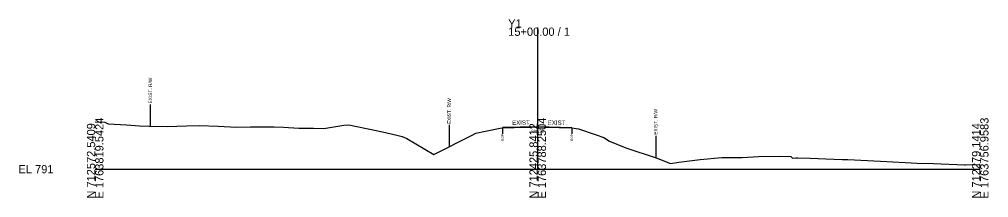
# Model space of a CAD drawing. Extents: x -26 to 1303, y -10 to 9524.
# Drawn here: x -25.7 to 302.8, y 4990.3 to 5050.9 of the extents above; entities that cross this region are included whole.
import ezdxf

# ---------------------------------------------------------------- set-up
doc = ezdxf.new("R2010")
doc.units = 0
for name, color, linetype in [('Default', 7, 'Continuous'), ('Exist Cross Section Cell', 7, 'Continuous'), ('Exist XS Center Line Elevation Label', 7, 'Continuous'), ('Exist XS Ground Line', 7, 'Continuous'), ('Old_Level_10', 7, 'Continuous'), ('Prop CMT Pvmt Surface Overlay', 7, 'Continuous'), ('Prop XS SE Text', 7, 'Continuous')]:
    doc.layers.add(name, color=color, linetype=linetype)

msp = doc.modelspace()

# ---------------------------------------------------------------- linework, layer by layer
at = {"layer": 'Exist Cross Section Cell'}
for p, q in [((150, 5000), (150, 5048.09)), ((0, 5000), (150, 5000)), ((150, 5000), (300, 5000))]:
    msp.add_line(p, q, dxfattribs=at)
at = {"layer": 'Exist XS Ground Line'}
msp.add_lwpolyline([(0, 5016.03), (3.22, 5015.93), (4.41, 5015.43), (10.66, 5015.01), (15.04, 5014.66), (18.3, 5014.61), (24.38, 5014.43), (30.9, 5014.74), (35.22, 5014.87), (41.66, 5014.55), (47.87, 5014.23), (52.7, 5014.36), (60.65, 5014.4), (63.79, 5014.3), (69.08, 5013.96), (74.01, 5013.95), (77.51, 5013.77), (84.24, 5014.96), (85.93, 5015.07), (95.19, 5013.13), (98.37, 5012.39), (102.66, 5011.47), (104.1, 5011.11), (105.64, 5010.41), (114.76, 5004.96), (128.03, 5011.68), (129, 5012.17), (132.35, 5012.88), (137.3, 5013.91), (138.06, 5014.08), (138.75, 5014.13), (139.22, 5014.15), (139.81, 5014.17), (140.7, 5014.19), (141.31, 5014.2), (141.91, 5014.2), (142.91, 5014.22), (144.47, 5014.26), (147.03, 5014.3), (147.61, 5014.31), (149.23, 5014.35), (149.55, 5014.35), (150.11, 5014.36), (151.62, 5014.32), (152.14, 5014.31), (153.37, 5014.3), (154.69, 5014.28), (156.62, 5014.2), (157.25, 5014.17), (157.66, 5014.16), (158.63, 5014.14), (159.58, 5014.11), (160.25, 5014.09), (161.57, 5014.05), (163.79, 5013.64), (169.8, 5011.7), (172.46, 5010.72), (174.33, 5009.51), (179.88, 5007.26), (190.2, 5003.88), (194.99, 5001.89), (197.89, 5002.37), (205.09, 5003.32), (212.36, 5003.92), (219.27, 5003.98), (224.82, 5004.27), (231.89, 5004.35), (235.83, 5004.28), (236.4, 5003.77), (237.53, 5003.81), (238.14, 5003.83), (242.3, 5003.69), (250.39, 5003.38), (253.32, 5003.29), (255.16, 5003.22), (257.34, 5003.13), (268.31, 5002.64), (276.61, 5002.16), (278.54, 5002.05), (284.14, 5001.88), (294.64, 5001.41), (295.06, 5001.41), (297.33, 5001.54), (300, 5001.47)], dxfattribs=at)
at = {"layer": 'Old_Level_10'}
for p, q in [((18.67, 5022), (18.67, 5014.6)), ((120, 5015.01), (120, 5007.61)), ((138.06, 5014.08), (138.06, 5012.03)), ((161.57, 5014.05), (161.57, 5012)), ((190, 5011.35), (190, 5003.94))]:
    msp.add_line(p, q, dxfattribs=at)
at = {"layer": 'Prop CMT Pvmt Surface Overlay'}
for p, q in [((138.06, 5014.21), (150, 5014.49)), ((138.06, 5014.08), (150, 5014.36)), ((150, 5014.49), (161.57, 5014.17)), ((150, 5014.36), (161.57, 5014.05))]:
    msp.add_line(p, q, dxfattribs=at)

# ---------------------------------------------------------------- texts
at = {"layer": 'Default'}
msp.add_text('-', height=0.0001, dxfattribs=at).set_placement((0, 5000))
at = {"layer": 'Exist Cross Section Cell'}
for s, p in [('Y1', (140, 5048.09)), ('15+00.00 / 1', (140, 5045.29)), ('EL 791', (-26, 4998.6))]:
    msp.add_text(s, height=2.8, dxfattribs=at).set_placement(p)
for s, p in [('E 1763819.5424', (2.8, 4990)), ('E 1763788.2504', (152.8, 4990)), ('E 1763756.9583', (302.8, 4990)), ('N 712572.5409', (0, 4990)), ('N 712425.8412', (150, 4990)), ('N 712279.1414', (300, 4990))]:
    msp.add_text(s, height=2.8, rotation=90, dxfattribs=at).set_placement(p)
at = {"layer": 'Exist XS Center Line Elevation Label'}
msp.add_text('805.36', height=1, dxfattribs=at).set_placement((147.86, 5012.36))
at = {"layer": 'Old_Level_10'}
for s, height, p in [('EXIST. R/W', 1.181, (19.26, 5022.3)), ('EXIST. R/W', 1.181, (120.59, 5015.31)), ('EXIST. R/W', 1.181, (190.59, 5011.65)), ('EOP', 0.787, (138.45, 5009.63)), ('EOP', 0.787, (161.96, 5009.6))]:
    msp.add_text(s, height=height, rotation=90, dxfattribs=at).set_placement(p)
at = {"layer": 'Prop XS SE Text'}
for rotation, p in [(1.1458, (141.33, 5014.99)), (358.8542, (153.37, 5015.09))]:
    msp.add_text('EXIST.', height=1.5, rotation=rotation, dxfattribs=at).set_placement(p)

doc.saveas('drawing.dxf')
